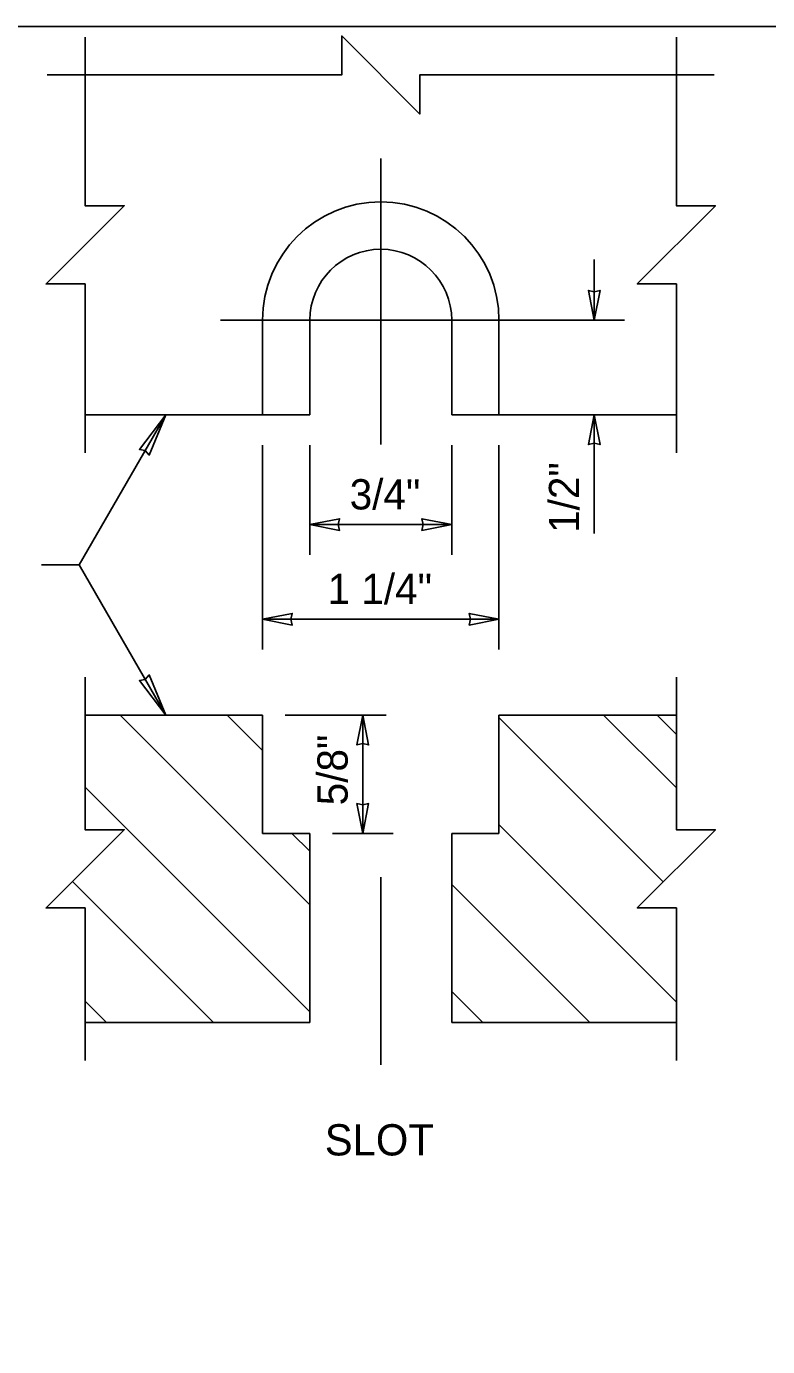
# Model space of a CAD drawing. Extents: x 99862 to 103151, y 100000 to 102076.
# Drawn here: x 101128 to 101520, y 101378 to 102076 of the extents above; entities that cross this region are included whole.
import ezdxf

# ---------------------------------------------------------------- set-up
doc = ezdxf.new("R2010")
doc.units = 0
for name, color, linetype in [('Level 1', 7, 'Continuous'), ('Level 15', 7, 'Continuous'), ('Level 17', 7, 'Continuous'), ('Level 2', 7, 'Continuous'), ('Level 20', 7, 'Continuous')]:
    doc.layers.add(name, color=color, linetype=linetype)

msp = doc.modelspace()

# ---------------------------------------------------------------- linework, layer by layer
at = {"layer": 'Level 1'}
msp.add_lwpolyline([(99862, 99999.5), (103151, 99999.5), (103151, 102075.5), (99862, 102075.5)], close=True, dxfattribs=at)
at = {"layer": 'Level 15'}
for p, q in [((101315.36, 101854.65), (101315.36, 102005.73)), ((101428.24, 101952.25), (101428.24, 101920.25)), ((101230.63, 101920.25), (101444.24, 101920.25)), ((101201.77, 101870.25), (101155.96, 101790.92)), ((101428.24, 101870.25), (101428.24, 101807.47)), ((101252.86, 101854.25), (101252.86, 101746.25)), ((101277.86, 101854.25), (101277.86, 101796.25)), ((101352.86, 101854.25), (101352.86, 101796.25)), ((101377.86, 101854.25), (101377.86, 101746.25)), ((101277.86, 101812.25), (101352.86, 101812.25)), ((101135.96, 101790.92), (101155.96, 101790.92)), ((101201.77, 101711.58), (101155.96, 101790.92)), ((101252.86, 101762.25), (101377.86, 101762.25)), ((101264.86, 101711.58), (101318.13, 101711.58)), ((101305.86, 101649.08), (101305.86, 101711.58)), ((101289.86, 101649.08), (101321.86, 101649.08)), ((101315.36, 101526.74), (101315.36, 101626.02))]:
    msp.add_line(p, q, dxfattribs=at)
for points in [[(101159.09, 102069.85), (101159.09, 101980.7), (101179.74, 101980.7), (101138.44, 101939.4), (101159.09, 101939.4), (101159.09, 101850.25)], [(101139.09, 102049.85), (101294.71, 102049.85), (101294.71, 102070.5), (101336, 102029.2), (101336, 102049.85), (101491.62, 102049.85)], [(101471.62, 102069.85), (101471.62, 101980.7), (101492.27, 101980.7), (101450.97, 101939.4), (101471.62, 101939.4), (101471.62, 101850.25)], [(101159.09, 101731.58), (101159.09, 101650.98), (101179.74, 101650.98), (101138.44, 101609.68), (101159.09, 101609.68), (101159.09, 101529.08)], [(101471.62, 101731.58), (101471.62, 101650.98), (101492.27, 101650.98), (101450.97, 101609.68), (101471.62, 101609.68), (101471.62, 101529.08)]]:
    msp.add_lwpolyline(points, dxfattribs=at)
for points in [[(101428.24, 101920.25), (101425.15, 101935.98), (101428.24, 101935.25), (101431.32, 101935.98)], [(101201.77, 101870.25), (101187.77, 101851.97), (101190.88, 101851.4), (101192.94, 101848.99)], [(101428.24, 101870.25), (101425.15, 101854.53), (101428.24, 101855.26), (101431.32, 101854.53)], [(101277.86, 101812.25), (101293.58, 101809.17), (101292.85, 101812.25), (101293.58, 101815.34)], [(101352.86, 101812.25), (101337.13, 101809.17), (101337.86, 101812.25), (101337.13, 101815.34)], [(101252.86, 101762.25), (101268.58, 101759.17), (101267.85, 101762.25), (101268.58, 101765.34)], [(101377.86, 101762.25), (101362.13, 101759.17), (101362.86, 101762.25), (101362.13, 101765.34)], [(101201.77, 101711.58), (101187.77, 101729.86), (101190.88, 101730.44), (101192.94, 101732.85)], [(101305.86, 101711.58), (101302.77, 101695.86), (101305.86, 101696.58), (101308.94, 101695.86)], [(101305.86, 101649.08), (101302.77, 101664.81), (101305.86, 101664.08), (101308.94, 101664.81)]]:
    msp.add_lwpolyline(points, close=True, dxfattribs=at)
at = {"layer": 'Level 17'}
for p, q in [((101277.86, 101611.32), (101177.59, 101711.58)), ((101252.86, 101692.88), (101234.16, 101711.58)), ((101471.62, 101673.07), (101433.11, 101711.58)), ((101471.62, 101701.36), (101461.39, 101711.58)), ((101464.71, 101623.42), (101377.86, 101710.27)), ((101277.86, 101554.75), (101159.09, 101673.51)), ((101277.86, 101639.6), (101268.37, 101649.08)), ((101471.62, 101559.93), (101377.86, 101653.7)), ((101226.95, 101549.08), (101152.4, 101623.64)), ((101425.9, 101549.08), (101352.86, 101622.13)), ((101369.34, 101549.08), (101352.86, 101565.56)), ((101170.38, 101549.08), (101159.09, 101560.38))]:
    msp.add_line(p, q, dxfattribs=at)
at = {"layer": 'Level 2'}
for p, q in [((101252.86, 101920.25), (101252.86, 101870.25)), ((101277.86, 101920.25), (101277.86, 101870.25)), ((101352.86, 101920.25), (101352.86, 101870.25)), ((101377.86, 101920.25), (101377.86, 101870.25)), ((101277.86, 101870.25), (101159.09, 101870.25)), ((101352.86, 101870.25), (101471.62, 101870.25)), ((101159.09, 101711.58), (101252.86, 101711.58)), ((101252.86, 101711.58), (101252.86, 101649.08)), ((101377.86, 101711.58), (101377.86, 101649.08)), ((101471.62, 101711.58), (101377.86, 101711.58)), ((101252.86, 101649.08), (101277.86, 101649.08)), ((101277.86, 101649.08), (101277.86, 101549.08)), ((101377.86, 101649.08), (101352.86, 101649.08)), ((101352.86, 101649.08), (101352.86, 101549.08)), ((101159.09, 101549.08), (101277.86, 101549.08)), ((101471.62, 101549.08), (101352.86, 101549.08))]:
    msp.add_line(p, q, dxfattribs=at)
for radius in [62.5, 37.5]:
    msp.add_arc((101315.36, 101920.25), radius, 360, 180, dxfattribs=at)

# ---------------------------------------------------------------- texts
at = {"layer": 'Level 1'}
msp.add_text('SLOT', height=16.5, dxfattribs=at).set_placement((101285.78, 101478.9))
at = {"layer": 'Level 20'}
for s, p in [('1/2"', (101420.24, 101807.87)), ('5/8"', (101297.86, 101663.91))]:
    msp.add_text(s, height=16, rotation=90, dxfattribs=at).set_placement(p)
for s, p in [('3/4"', (101298.93, 101820.25)), ('1 1/4"', (101287.27, 101770.25))]:
    msp.add_text(s, height=16, dxfattribs=at).set_placement(p)

doc.saveas('drawing.dxf')
